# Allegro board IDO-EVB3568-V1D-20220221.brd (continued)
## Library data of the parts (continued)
D2-D9 D11-D14 D19 D20 D22-D46 D54 D55 D59 D61-D65 D94-D102 D108-D111 = DI-ESD
D15-D18 D21 D47 D48 D52 D53 D57 D58 D66-D70 = DI-ESD-MKT642U05
D71-D74 = DI-ESD-SRV05-4
D75 D104-D106 = DI-TVS-D
D78 D81 D85 D87 D89 D91 D103 = DI-TVS-BST23A122V
F1 = FUSE-SMD1812: User Part Number: HAMP; Tolerance: #TOL
F2-F15 = FUSE-SMD1206
H1-H4 = HOLE: User Part Number: pn; Tolerance: RichardLC
H5 = HOLE: Tolerance: RichardLC; User Part Number: pn
J1 = J-H-4P
J2 = J-DC-044A-2_5
J3 = J-TF-01A
J4 = J-A-3P: Tolerance: #TOL; User Part Number: HAMP
J5 = J-USB-4AFX2-DIP_1
J6 = SATA_DIP_0
J7 J16 = J-H-2P
J8 J9 = J-USB-4AFx2-DIP_2: Tolerance: #TOL; User Part Number: HAMP
J10-J12 = J-H-4P_0
J13 J21 J27 = J-H-6P
J14 = J-H-8P
J15 = J-PJ-316A-6A
J17 J32-J36 = J-A-4P: Tolerance: #TOL; User Part Number: HAMP
J18 = J-HDMI-19P
J19 = J-HDR-D-20: User Part Number: pn; Tolerance: RichardLC
J20 J25 = J-HDR-6: User Part Number: pn; Tolerance: RichardLC
J22 J23 = J-FPC05-40P: User Part Number: DENG
J24 = J-FPC05-6P: User Part Number: DENG
J26 = J-HDR-D-30: User Part Number: pn; Tolerance: RichardLC
J28 = J-FPC05-24P
J29 = RF-IPEX-20279
J30 J31 = J-RJ45-HR911130C: User Part Number: HAMP; Tolerance: #TOL
J39 = J-A-5P: Tolerance: #TOL; User Part Number: HAMP
J40 = J-A-2P
J41 = J-MINIPCIE-52P_0
L1-L3 L27 L28 L31-L33 L49 = L-IND
L5-L10 L12 L14 L15 L23-L26 L46 L47 = L-CMLS-ACM2012
L11 L13 L16-L22 L29 L30 L48 = FB-0603
L34-L45 = FB-0402
L50 = L-CMLS-ACM2012-1
LED1 = D-LED-DIP-2: User Part Number: DENG
LED2 = D-LED0603
M1-M4 = MARK
M5 = MODE-204P_2
Q1 Q2 Q7 Q10 Q13 Q16 = S-NPN
Q3-Q5 Q8 Q11 Q15 Q17 = N-MOS-Q
Q6 Q9 Q12 = P-MOS
R3-R10 R12-R37 R39-R57 R59-R62 R68-R105 R108-R116 R119-R122 R125-R166 R168 R170-R173 R175-R179 R181-R264 R266-R278 R282 R284 R286-R288 R291 R293-R295 R299-R302 R305-R309 R312 R313 R316-R367 R370-R391 = R-0402
R106 R107 R117 R118 R174 R265 R368 R369 = R-0805
R289 R292 R296 R298 R303 R304 R310 R311 = R-0603
R290 R297 = R-1206
SIM1 = J-SIM-021_0
SW1 = SW-K2-1109DE-C4SW-01
TP1-TP27 = TP-TEST: User Part Number: pn; Tolerance: RichardLC
U1 U39 = U-SY8105ADC_0
U2 U37 = U-TLV62569DBVR
U4-U7 U9-U12 U40 = U-SY6280AAC
U8 = U-FE2.1: User Part Number: HAMP; Tolerance: #TOL
U13 = U-NS4205
U14 U18 = U-74LVC1G125GW-125
U15 U16 = U-SY7201A_2
U17 = GM8775C
U19 = U-ME6211C18M5G-N
U20 = U-ME6211C15M5G-N
U21 = U-ME6211C28M5G-N
U23 = MODULE_AP6XXX
U24 U25 = Ethernet_RTL8211F
U26 U27 = U-SP3232EEN-L-TR
U28 U30 = U-MC74VHC1G04DFT2G
U29 U31 = U-SP485EEN-L-TR
U32 U33 = U-TJA1057GT-3J
U34 = U-PCF85063ATT
U35 = Sensor_MPU6500_1
U36 = PCIE_M2_NGFF-B-KEY_2
U38 = 5962-87786_1
XT1 XT3-XT5 = XTAL-4P
XT6 = XTAL-2P

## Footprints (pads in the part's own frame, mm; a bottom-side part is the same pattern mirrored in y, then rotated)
C0402L
  rect 0.49x0.54 smd: 1(-0.43,0) 2(0.43,0)
C0603L
  rect 0.75x0.9 smd: 1(-0.7,0) 2(0.7,0)
C0805L
  rect 0.95x1.35 smd: 1(-0.8,0) 2(0.8,0)
C1206L
  rect 0.95x1.7 smd: 1(-1.4,0) 2(1.4,0)
CAPAE660X770
  rect 3.15x1.6 smd: 1(-2.45,0) 2(2.45,0)
CMLP-ACM4532
  rect 1.2x1 smd: 1(-1.65,1.15) 2(-1.65,-1.15) 3(1.65,-1.15) 4(1.65,1.15)
CMLS-ACM2012
  rect 0.7x0.45 smd: 1(-0.85,0.4) 2(-0.85,-0.4) 3(0.85,-0.4) 4(0.85,0.4)
DC-044A-2_5
  round 2.3 hole 2.3 unplated: (4.1,0)
  rect 3x1.6 hole 2x0.8: 2(10.201,5.199) 3(10.201,0) 4(10.201,-3.401)
  rect 2.5x1 hole 2x0.6: 5(3,6.149) 6(3,-3.65)
DURAL_USB_AF_2X
  round 1.001 hole 0.701: 1(-3.5,0.686) 2(-1.001,0.686) 3(1.001,0.686) 4(3.5,0.686) 10(-3.5,3.327) 11(-1.001,3.327) 12(1.001,3.327) 13(3.5,3.327)
  round 2.901 hole 2.311: S1(-6.571,3.68) S2(6.571,3.68) S3(-6.571,-1.999) S4(6.571,-1.999)
ESD-DFN2510A-10
  rect 0.2x0.68 smd: 1(-1,-0.437) 2(-0.5,-0.437) 4(0.5,-0.437) 5(1,-0.437) 6(1,0.437) 7(0.5,0.437) 9(-0.5,0.437) 10(-1,0.437)
  rect 0.4x0.75 smd: 3(0,-0.395) 8(0,0.395)
FE2_1-LQFP48
  oval 1.651x0.279 smd: 1(-4.275,2.751) 2(-4.275,2.25) 3(-4.275,1.75) 4(-4.275,1.25) 5(-4.275,0.749) 6(-4.275,0.249) 7(-4.275,-0.249) 8(-4.275,-0.749) 9(-4.275,-1.25) 10(-4.275,-1.75) 11(-4.275,-2.25) 12(-4.275,-2.751) 25(4.275,-2.751) 26(4.275,-2.25) 27(4.275,-1.75) 28(4.275,-1.25) 29(4.275,-0.749) 30(4.275,-0.249) 31(4.275,0.249) 32(4.275,0.749) 33(4.275,1.25) 34(4.275,1.75) 35(4.275,2.25) 36(4.275,2.751)
  oval 0.279x1.651 smd: 13(-2.751,-4.275) 14(-2.25,-4.275) 15(-1.75,-4.275) 16(-1.25,-4.275) 17(-0.749,-4.275) 18(-0.249,-4.275) 19(0.249,-4.275) 20(0.749,-4.275) 21(1.25,-4.275) 22(1.75,-4.275) 23(2.25,-4.275) 24(2.751,-4.275) 37(2.751,4.275) 38(2.25,4.275) 39(1.75,4.275) 40(1.25,4.275) 41(0.749,4.275) 42(0.249,4.275) 43(-0.249,4.275) 44(-0.749,4.275) 45(-1.25,4.275) 46(-1.75,4.275) 47(-2.25,4.275) 48(-2.751,4.275)
FPC05-FDW-6P
  rect 0.305x1.27 smd: 1(1.25,1.575) 2(0.75,1.575) 3(0.25,1.575) 4(-0.25,1.575) 5(-0.75,1.575) 6(-1.25,1.575)
  rect 1.803x3.048 smd: 7(3.05,-1.27) 8(-3.05,-1.27)
FPC05-FDW-40P
  rect 0.305x1.27 smd: 1(9.751,1.575) 2(9.251,1.575) 3(8.75,1.575) 4(8.25,1.575) 5(7.749,1.575) 6(7.249,1.575) 7(6.749,1.575) 8(6.251,1.575) 9(5.751,1.575) 10(5.25,1.575) 11(4.75,1.575) 12(4.249,1.575) 13(3.749,1.575) 14(3.251,1.575) 15(2.751,1.575) 16(2.25,1.575) 17(1.75,1.575) 18(1.25,1.575) 19(0.749,1.575) 20(0.249,1.575) 21(-0.249,1.575) 22(-0.749,1.575) 23(-1.25,1.575) 24(-1.75,1.575) 25(-2.25,1.575) 26(-2.751,1.575) 27(-3.251,1.575) 28(-3.749,1.575) 29(-4.249,1.575) 30(-4.75,1.575) 31(-5.25,1.575) 32(-5.751,1.575) 33(-6.251,1.575) 34(-6.749,1.575) 35(-7.249,1.575) 36(-7.749,1.575) 37(-8.25,1.575) 38(-8.75,1.575) 39(-9.251,1.575) 40(-9.751,1.575)
  rect 1.803x3.048 smd: 41(11.549,-1.001) 42(-11.549,-1.001)
FPC05-ZDW-24P
  rect 1.2x0.4 smd: 1(-0.975,5.75) 2(0.975,5.25) 3(-0.975,4.75) 4(0.975,4.25) 5(-0.975,3.75) 6(0.975,3.25) 7(-0.975,2.75) 8(0.975,2.25) 9(-0.975,1.75) 10(0.975,1.25) 11(-0.975,0.75) 12(0.975,0.25) 13(-0.975,-0.25) 14(0.975,-0.75) 15(-0.975,-1.25) 16(0.975,-1.75) 17(-0.975,-2.25) 18(0.975,-2.75) 19(-0.975,-3.25) 20(0.975,-3.75) 21(-0.975,-4.25) 22(0.975,-4.75) 23(-0.975,-5.25) 24(0.975,-5.75)
  rect 2.4x2 smd: 25(0,7.55) 26(0,-7.55)
HDMIA19_HDMI_01A-NEW
  rect 0.3x2.6 smd: 1(0,0) 2(0.5,0) 3(1,0) 4(1.5,0) 5(2,0) 6(2.5,0) 7(3,0) 8(3.5,0) 9(4,0) 10(4.5,0) 11(5,0) 12(5.5,0) 13(6,0) 14(6.5,0) 15(7,0) 16(7.5,0) 17(8,0) 18(8.5,0) 19(9,0)
  oval 1.5x3.5 hole 0.9x2.7: 20(11.75,0.76) 21(-2.75,0.76)
  oval 1.5x2.5 hole 0.9x1.7: 22(-2.75,6.72) 23(11.75,6.72)
HDR200MA-1X6
  rect 1.5x1.5 hole 0.8: 1(0,0)
  round 1.5 hole 0.8: 2(2,0) 3(4,0) 4(6,0) 5(8,0) 6(10,0)
HDR200MRA-2X10
  rect 1.5x1.5 hole 0.7: 1(0,0)
  round 1.3 hole 0.7: 2(0,2) 3(2,0) 4(2,2) 5(4,0) 6(4,2) 7(6,0) 8(6,2) 9(8,0) 10(8,2) 11(10,0) 12(10,2) 13(12,0) 14(12,2) 15(14,0) 16(14,2) 17(16,0) 18(16,2) 19(18,0) 20(18,2)
HDR200MRA-2X15
  rect 1.5x1.5 hole 0.7: 1(0,0)
  round 1.3 hole 0.7: 2(0,2) 3(2,0) 4(2,2) 5(4,0) 6(4,2) 7(6,0) 8(6,2) 9(8,0) 10(8,2) 11(10,0) 12(10,2) 13(12,0) 14(12,2) 15(14,0) 16(14,2) 17(16,0) 18(16,2) 19(18,0) 20(18,2) 21(20,0) 22(20,2) 23(22,0) 24(22,2) 25(24,0) 26(24,2) 27(26,0) 28(26,2) 29(28,0) 30(28,2)
HR911130X
  round 2.997 hole 3.251 unplated: (-5.715,-3.051) (5.715,-3.051)
  round 1.524 hole 0.889: 1(5.715,-11.941) 2(4.445,-9.401) 3(3.175,-11.941) 4(1.905,-9.401) 5(0.635,-11.941) 6(-0.635,-9.401) 7(-1.905,-11.941) 8(-3.175,-9.401) 9(-4.445,-11.941) 10(-5.715,-9.401)
  round 1.651 hole 1.016: 11(6.624,1.849) 12(4.084,1.849) 13(-4.084,1.849) 14(-6.624,1.849)
  round 2.54 hole 1.651: SH1(-7.846,-6.101) SH2(7.846,-6.101)
IPEX-20279-001E
  rect 1.2x0.8 smd: 1(-1.525,0)
  rect 1.5x1.2 smd: 2(1.8,0)
  rect 2.65x1.2 smd: 3(0,-1.5) 4(0,1.5)
L0402
  rect 0.59x0.72 smd: 1(-0.48,0) 2(0.48,0)
L0603
  rect 0.8x1.02 smd: 1(-0.65,0) 2(0.65,0)
L2520
  rect 0.7x2 smd: 1(-1.05,0) 2(1.05,0)
L4040
  rect 1.65x3.35 smd: 1(-1.5,0) 2(1.5,0)
LED0603
  rect 0.9x0.95 smd: A(0.8,0) C(-0.8,0)
LED_P254_2X2DIP
  round 1.422 hole 0.914: 1(-1.27,-1.27) 2(1.27,-1.27) 3(-1.27,1.27) 4(1.27,1.27)
M_MINIPCIE_SOCKET_CK
  round 1.143 hole 1.143 unplated: (-12.499,0)
  round 1.651 hole 1.651 unplated: (12.499,0)
  rect 0.508x2.032 smd: 1(11.801,4.1) 2(11.399,-4.1) 3(11.001,4.1) 4(10.599,-4.1) 5(10.201,4.1) 6(9.799,-4.1) 7(9.4,4.1) 8(8.999,-4.1) 9(8.6,4.1) 10(8.199,-4.1) 11(7.8,4.1) 12(7.399,-4.1) 13(7,4.1) 14(6.599,-4.1) 15(6.2,4.1) 16(5.801,-4.1) 17(2.2,4.1) 18(1.801,-4.1) 19(1.399,4.1) 20(1.001,-4.1) 21(0.599,4.1) 22(0.201,-4.1) 23(-0.201,4.1) 24(-0.599,-4.1) 25(-1.001,4.1) 26(-1.399,-4.1) 27(-1.801,4.1) 28(-2.2,-4.1) 29(-2.601,4.1) 30(-3,-4.1) 31(-3.401,4.1) 32(-3.8,-4.1) 33(-4.201,4.1) 34(-4.6,-4.1) 35(-4.999,4.1) 36(-5.4,-4.1) 37(-5.801,4.1) 38(-6.2,-4.1) 39(-6.599,4.1) 40(-7,-4.1) 41(-7.399,4.1) 42(-7.8,-4.1) 43(-8.199,4.1) 44(-8.6,-4.1) 45(-8.999,4.1) 46(-9.4,-4.1) 47(-9.799,4.1) 48(-10.201,-4.1) 49(-10.599,4.1) 50(-11.001,-4.1) 51(-11.399,4.1) 52(-11.801,-4.1)
  rect 2.413x3.302 smd: 55(-14.651,3.5) 56(14.651,3.5)
MARK
  round 1 smd: 1(0,0)
MD44_AP6XXX
  rect 1.2x0.5 smd: 1(-5.7,4.5) 2(-5.7,3.6) 3(-5.7,2.7) 4(-5.7,1.8) 5(-5.7,0.9) 6(-5.7,0) 7(-5.7,-0.9) 8(-5.7,-1.8) 9(-5.7,-2.7) 10(-5.7,-3.6) 11(-5.7,-4.5) 23(5.7,-4.5) 24(5.7,-3.6) 25(5.7,-2.7) 26(5.7,-1.8) 27(5.7,-0.9) 28(5.7,0) 29(5.7,0.9) 30(5.7,1.8) 31(5.7,2.7) 32(5.7,3.6) 33(5.7,4.5)
  rect 0.5x1.2 smd: 12(-4.5,-5.7) 13(-3.6,-5.7) 14(-2.7,-5.7) 15(-1.8,-5.7) 16(-0.9,-5.7) 17(0,-5.7) 18(0.9,-5.7) 19(1.8,-5.7) 20(2.7,-5.7) 21(3.6,-5.7) 22(4.5,-5.7) 34(4.5,5.7) 35(3.6,5.7) 36(2.7,5.7) 37(1.8,5.7) 38(0.9,5.7) 39(0,5.7) 40(-0.9,5.7) 41(-1.8,5.7) 42(-2.7,5.7) 43(-3.6,5.7) 44(-4.5,5.7)
  round 0.6 smd: 45(-2.7,3.6) 46(-0.9,3.6) 47(0.9,3.6)
MPU6500-QFN-24
  custom 0.05x0.05 smd: 1(-1.55,1) 2(-1.55,0.6) 3(-1.55,0.2) 4(-1.55,-0.2) 5(-1.55,-0.6) 6(-1.55,-1) 7(-1,-1.55) 8(-0.6,-1.55) 9(-0.2,-1.55) 10(0.2,-1.55) 11(0.6,-1.55) 12(1,-1.55) 13(1.55,-1) 14(1.55,-0.6) 15(1.55,-0.2) 16(1.55,0.2) 17(1.55,0.6) 18(1.55,1) 19(1,1.55) 20(0.6,1.55) 21(0.2,1.55) 22(-0.2,1.55) 23(-0.6,1.55) 24(-1,1.55)
  custom 0.375x0.375 smd: 25(0,0)
MTG250_600
  round 6 hole 1.7: 1(0,0)
MTG300_500
  round 5 hole 3: 1(0,0)
MX125T-S-2A
  rect 0.635x1.6 smd: 1(-0.625,0) 2(0.625,0)
  rect 2.134x3.048 smd: 3(3.175,2.9) 4(-3.175,2.9)
MX125T-S-3A
  rect 0.813x1.626 smd: 1(-1.25,2.9) 2(0,2.9) 3(1.25,2.9)
  rect 2.134x3.048 smd: 4(3.8,0) 5(-3.8,0)
NS4205-SOP16
  rect 1.905x0.635 smd: 1(0,0) 2(0,-1.27) 3(0,-2.54) 4(0,-3.81) 5(0,-5.08) 6(0,-6.35) 7(0,-7.62) 8(0,-8.89) 9(6.096,-8.89) 10(6.096,-7.62) 11(6.096,-6.35) 12(6.096,-5.08) 13(6.096,-3.81) 14(6.096,-2.54) 15(6.096,-1.27) 16(6.096,0)
PB-SIDE-P-4_5X4_5
  round 1.3 hole 0.8: 1(0,0) 2(0,-3.1) 3(-1.95,-1.55)
PCA9539PW-TSSOP24
  oval 1.5x0.45 smd: 1(-3.5,3.575) 2(-3.5,2.925) 3(-3.5,2.275) 4(-3.5,1.625) 5(-3.5,0.975) 6(-3.5,0.325) 7(-3.5,-0.325) 8(-3.5,-0.975) 9(-3.5,-1.625) 10(-3.5,-2.275) 11(-3.5,-2.925) 12(-3.5,-3.575) 13(3.5,-3.575) 14(3.5,-2.925) 15(3.5,-2.275) 16(3.5,-1.625) 17(3.5,-0.975) 18(3.5,-0.325) 19(3.5,0.325) 20(3.5,0.975) 21(3.5,1.625) 22(3.5,2.275) 23(3.5,2.925) 24(3.5,3.575)
PCF85063ATT-TSSOP8
  rect 1.905x0.381 smd: 1(-2.1,0.975) 2(-2.1,0.325) 3(-2.1,-0.325) 4(-2.1,-0.975) 5(2.1,-0.975) 6(2.1,-0.325) 7(2.1,0.325) 8(2.1,0.975)
PCIE_M2_NGFF-B-KEY
  round 1.6 hole 1.6 unplated: (0,0)
  round 1.092 hole 1.092 unplated: (20.003,0)
  rect 0.305x1.549 smd: 1(19.251,-5.278) 2(18.999,2.273) 3(18.75,-5.278) 4(18.504,2.273) 5(18.247,-5.278) 6(17.996,2.273) 7(17.752,-5.278) 8(17.501,2.273) 9(17.249,-5.278) 10(17.005,2.273) 11(16.749,-5.278) 20(14.503,2.273) 21(14.249,-5.278) 22(14,2.273) 23(13.749,-5.278) 24(13.5,2.273) 25(13.249,-5.278) 26(13,2.273) 27(12.748,-5.278) 28(12.499,2.273) 29(12.248,-5.278) 30(11.999,2.273) 31(11.748,-5.278) 32(11.501,2.273) 33(11.25,-5.278) 34(11.001,2.273) 35(10.749,-5.278) 36(10.503,2.273) 37(10.251,-5.278) 38(10,2.273) 39(9.751,-5.278) 40(9.5,2.273) 41(9.251,-5.278) 42(8.999,2.273) 43(8.75,-5.278) 44(8.501,2.273) 45(8.25,-5.278) 46(8.001,2.273) 47(7.75,-5.278) 48(7.501,2.273) 49(7.252,-5.278) 50(7,2.273) 51(6.749,-5.278) 52(6.5,2.273) 53(6.253,-5.278) 54(6.002,2.273) 55(5.751,-5.278) 56(5.502,2.273) 57(5.25,-5.278) 58(5.001,2.273) 59(4.75,-5.278) 60(4.501,2.273) 61(4.249,-5.278) 62(4,2.273) 63(3.749,-5.278) 64(3.5,2.273) 65(3.249,-5.278) 66(3,2.273) 67(2.751,-5.278) 68(2.502,2.273) 69(2.243,-5.278) 70(2.002,2.273) 71(1.75,-5.278) 72(1.501,2.273) 73(1.25,-5.278) 74(1.001,2.273) 75(0.749,-5.278)
  round 6 hole 4.2: MH1(9.995,49.686)
  rect 1.194x2.743 smd: MTG76(20.358,-4.496) MTG77(-0.343,-4.496)
PH200-2A
  rect 1.524x1.524 hole 1.016: 1(4.064,0)
  round 1.524 hole 1.016: 2(2.032,0)
PH200-4A
  rect 1.27x1.27 hole 0.813: 1(6.096,0)
  round 1.27 hole 0.813: 2(4.064,0) 3(2.032,0) 4(0,0)
PH200-6A
  rect 1.27x1.27 hole 0.813: 1(6.096,0)
  round 1.27 hole 0.813: 2(4.064,0) 3(2.032,0) 4(0,0) 5(-2.032,0) 6(-4.064,0)
PH200-6AW
  rect 1.524x1.524 hole 1.016: 1(4.064,0)
  round 1.524 hole 1.016: 2(2.032,0) 3(0,0) 4(-2.032,0) 5(-4.039,0) 6(-6.045,0)
PH200-8A
  rect 1.27x1.27 hole 0.813: 1(6.096,0)
  round 1.27 hole 0.813: 2(4.064,0) 3(2.032,0) 4(0,0) 5(-2.032,0) 6(-4.064,0) 7(-6.096,0) 8(-8.128,0)
PH200-S-4AWZ
  rect 1.016x7.5 smd: 1(-3,2) 2(-1,2) 3(1,2) 4(3,2)
  rect 1.524x3.404 smd: 5(-5.35,5.75) 6(5.35,5.75)
PH200-S-5AWZ
  rect 1.016x7.5 smd: 1(-3,2) 2(-1,2) 3(1,2) 4(3,2) 5(5,2)
  rect 1.524x3.404 smd: 6(-5.35,5.75) 7(7.35,5.75)
PJ-316A-6A
  round 1.397 hole 1.397 unplated: (-10.55,0)
  rect 1.778x2.159 smd: 1(-2.75,3.75) 2(-9.3,-4.15) 3(-5.5,3.75) 4(-2.75,-4.15) 5(-11.5,-4.15) 6(-10.55,3.75)
QFN50P700X700X100-49AN
  custom 0.075x0.075 smd: 1(-3.45,2.75) 2(-3.45,2.25) 3(-3.45,1.75) 4(-3.45,1.25) 5(-3.45,0.75) 6(-3.45,0.25) 7(-3.45,-0.25) 8(-3.45,-0.75) 9(-3.45,-1.25) 10(-3.45,-1.75) 11(-3.45,-2.25) 12(-3.45,-2.75) 13(-2.75,-3.45) 14(-2.25,-3.45) 15(-1.75,-3.45) 16(-1.25,-3.45) 17(-0.75,-3.45) 18(-0.25,-3.45) 19(0.25,-3.45) 20(0.75,-3.45) 21(1.25,-3.45) 22(1.75,-3.45) 23(2.25,-3.45) 24(2.75,-3.45) 25(3.45,-2.75) 26(3.45,-2.25) 27(3.45,-1.75) 28(3.45,-1.25) 29(3.45,-0.75) 30(3.45,-0.25) 31(3.45,0.25) 32(3.45,0.75) 33(3.45,1.25) 34(3.45,1.75) 35(3.45,2.25) 36(3.45,2.75) 37(2.75,3.45) 38(2.25,3.45) 39(1.75,3.45) 40(1.25,3.45) 41(0.75,3.45) 42(0.25,3.45) 43(-0.25,3.45) 44(-0.75,3.45) 45(-1.25,3.45) 46(-1.75,3.45) 47(-2.25,3.45) 48(-2.75,3.45)
  rect 5.25x5.25 smd: 49(0,0)
R0402L
  rect 0.47x0.52 smd: 1(-0.43,0) 2(0.43,0)
R0603L
  rect 0.7x0.92 smd: 1(-0.6,0) 2(0.6,0)
R0805L
  rect 0.85x1.3 smd: 1(-0.85,0) 2(0.85,0)
R1206L
  rect 0.85x1.7 smd: 1(-1.4,0) 2(1.4,0)
RTL8211F-CG-QFN40
  rect 0.7x0.2 smd: 1(-2.35,1.8) 2(-2.35,1.4) 3(-2.35,1) 4(-2.35,0.6) 5(-2.35,0.2) 6(-2.35,-0.2) 7(-2.35,-0.6) 8(-2.35,-1) 9(-2.35,-1.4) 10(-2.35,-1.8) 21(2.35,-1.8) 22(2.35,-1.4) 23(2.35,-1) 24(2.35,-0.6) 25(2.35,-0.2) 26(2.35,0.2) 27(2.35,0.6) 28(2.35,1) 29(2.35,1.4) 30(2.35,1.8)
  rect 0.2x0.7 smd: 11(-1.8,-2.35) 12(-1.4,-2.35) 13(-1,-2.35) 14(-0.6,-2.35) 15(-0.2,-2.35) 16(0.2,-2.35) 17(0.6,-2.35) 18(1,-2.35) 19(1.4,-2.35) 20(1.8,-2.35) 31(1.8,2.35) 32(1.4,2.35) 33(1,2.35) 34(0.6,2.35) 35(0.2,2.35) 36(-0.2,2.35) 37(-0.6,2.35) 38(-1,2.35) 39(-1.4,2.35) 40(-1.8,2.35)
  rect 3.2x3.2 smd: 41(0,0)
SATA30_7P_V_DIP
  oval 0.92x1.27 hole 0.74: 1(0,0) 2(-1.27,1) 3(-2.54,1) 4(-3.81,0) 5(-5.08,1) 6(-6.35,1) 7(-7.62,0)
  round 2.35 hole 1.35: 8(2.67,0.5) 9(-10.29,0.5)
SIM-91288-021
  rect 2.54x1.397 smd: C1(-0.051,12.319) C2(-0.051,9.779) C3(-0.051,7.239) C5(-23.622,12.319) C6(-23.622,9.779) C7(-23.622,7.239) CD1(-0.051,-0.051) CD2(-23.622,-0.051)
SMA_DO-214AC
  rect 1.85x1.45 smd: A(1.95,0) C(-1.95,0)
SMAF
  rect 1.43x1.53 smd: A(-1.84,0) C(1.84,0)
SMD1206
  rect 1.25x1.65 smd: 1(-1.5,0) 2(1.5,0)
SMD1812
  rect 2.032x3.302 smd: 1(-2.159,0) 2(2.159,0)
SOD123
  rect 0.8x0.75 smd: A(1.7,0) C(-1.7,0)
SOD523
  rect 0.65x0.5 smd: A(0.9,0) C(-0.9,0)
SOM3568-204P
  oval 0.55x1.4 smd: 1(2.489,0.708) 2(3.489,0.708) 3(4.489,0.708) 4(5.489,0.708) 5(6.489,0.708) 6(7.489,0.708) 7(8.489,0.708) 8(9.489,0.708) 9(10.489,0.708) 10(11.489,0.708) 11(12.489,0.708) 12(13.489,0.708) 13(14.489,0.708) 14(15.489,0.708) 15(16.489,0.708) 16(17.489,0.708) 17(18.489,0.708) 18(19.489,0.708) 19(20.489,0.708) 20(21.489,0.708) 21(22.489,0.708) 22(23.489,0.708) 23(24.489,0.708) 24(25.489,0.708) 25(26.489,0.708) 26(27.489,0.708) 27(28.489,0.708) 28(29.489,0.708) 29(30.489,0.708) 30(31.489,0.708) 31(32.489,0.708) 32(33.489,0.708) 33(34.489,0.708) 34(35.489,0.708) 35(36.489,0.708) 36(37.489,0.708) 37(38.489,0.708) 38(39.489,0.708) 39(40.489,0.708) 40(41.489,0.708) 41(42.489,0.708) 42(43.489,0.708) 43(44.489,0.708) 44(45.489,0.708) 45(46.489,0.708) 46(47.489,0.708) 47(48.489,0.708) 48(49.489,0.708) 49(50.489,0.708) 50(51.489,0.708) 51(52.489,0.708) 52(53.489,0.708) 53(54.489,0.708) 54(55.489,0.708) 55(56.489,0.708) 56(57.489,0.708) 57(58.489,0.708) 58(59.489,0.708) 103(59.489,47.044) 104(58.489,47.044) 105(57.489,47.044) 106(56.489,47.044) 107(55.489,47.044) 108(54.489,47.044) 109(53.489,47.044) 110(52.489,47.044) 111(51.489,47.044) 112(50.489,47.044) 113(49.489,47.044) 114(48.489,47.044) 115(47.489,47.044) 116(46.489,47.044) 117(45.489,47.044) 118(44.489,47.044) 119(43.489,47.044) 120(42.489,47.044) 121(41.489,47.044) 122(40.489,47.044) 123(39.489,47.044) 124(38.489,47.044) 125(37.489,47.044) 126(36.489,47.044) 127(35.489,47.044) 128(34.489,47.044) 129(33.489,47.044) 130(32.489,47.044) 131(31.489,47.044) 132(30.489,47.044) 133(29.489,47.044) 134(28.489,47.044) 135(27.489,47.044) 136(26.489,47.044) 137(25.489,47.044) 138(24.489,47.044) 139(23.489,47.044) 140(22.489,47.044) 141(21.489,47.044) 142(20.489,47.044) 143(19.489,47.044) 144(18.489,47.044) 145(17.489,47.044) 146(16.489,47.044) 147(15.489,47.044) 148(14.489,47.044) 149(13.489,47.044) 150(12.489,47.044) 151(11.489,47.044) 152(10.489,47.044) 153(9.489,47.044) 154(8.489,47.044) 155(7.489,47.044) 156(6.489,47.044) 157(5.489,47.044) 158(4.489,47.044) 159(3.489,47.044) 160(2.489,47.044)
  oval 1.4x0.55 smd: 59(61.268,2.377) 60(61.268,3.377) 61(61.268,4.377) 62(61.268,5.377) 63(61.268,6.377) 64(61.268,7.377) 65(61.268,8.377) 66(61.268,9.377) 67(61.268,10.377) 68(61.268,11.377) 69(61.268,12.377) 70(61.268,13.377) 71(61.268,14.377) 72(61.268,15.377) 73(61.268,16.377) 74(61.268,17.377) 75(61.268,18.377) 76(61.268,19.377) 77(61.268,20.377) 78(61.268,21.377) 79(61.268,22.377) 80(61.268,23.377) 81(61.268,24.377) 82(61.268,25.377) 83(61.268,26.377) 84(61.268,27.377) 85(61.268,28.377) 86(61.268,29.377) 87(61.268,30.377) 88(61.268,31.377) 89(61.268,32.377) 90(61.268,33.377) 91(61.268,34.377) 92(61.268,35.377) 93(61.268,36.377) 94(61.268,37.377) 95(61.268,38.377) 96(61.268,39.377) 97(61.268,40.377) 98(61.268,41.377) 99(61.268,42.377) 100(61.268,43.377) 101(61.268,44.377) 102(61.268,45.377) 161(0.708,45.377) 162(0.708,44.377) 163(0.708,43.377) 164(0.708,42.377) 165(0.708,41.377) 166(0.708,40.377) 167(0.708,39.377) 168(0.708,38.377) 169(0.708,37.377) 170(0.708,36.377) 171(0.708,35.377) 172(0.708,34.377) 173(0.708,33.377) 174(0.708,32.377) 175(0.708,31.377) 176(0.708,30.377) 177(0.708,29.377) 178(0.708,28.377) 179(0.708,27.377) 180(0.708,26.377) 181(0.708,25.377) 182(0.708,24.377) 183(0.708,23.377) 184(0.708,22.377) 185(0.708,21.377) 186(0.708,20.377) 187(0.708,19.377) 188(0.708,18.377) 189(0.708,17.377) 190(0.708,16.377) 191(0.708,15.377) 192(0.708,14.377) 193(0.708,13.377) 194(0.708,12.377) 195(0.708,11.377) 196(0.708,10.377) 197(0.708,9.377) 198(0.708,8.377) 199(0.708,7.377) 200(0.708,6.377) 201(0.708,5.377) 202(0.708,4.377) 203(0.708,3.377) 204(0.708,2.377)
  rect 1.524x1.524 smd: 205(3.81,8.895) 206(3.81,11.405) 207(3.81,13.914)
SOP8-P127-390X490
  rect 1.35x0.55 smd: 1(-2.6,1.905) 2(-2.6,0.635) 3(-2.6,-0.635) 4(-2.6,-1.905) 5(2.6,-1.905) 6(2.6,-0.635) 7(2.6,0.635) 8(2.6,1.905)
SOT23
  rect 1.05x0.65 smd: 1(-1.15,0.95) 2(-1.15,-0.95) 3(1.15,0)
SOT23-5
  rect 1.1x0.6 smd: 1(-1.35,0.95) 2(-1.35,0) 3(-1.35,-0.95) 4(1.35,-0.95) 5(1.35,0.95)
SOT23-6
  rect 1.05x0.6 smd: 1(-1.35,0.95) 2(-1.35,0) 3(-1.35,-0.95) 4(1.35,-0.95) 5(1.35,0) 6(1.35,0.95)
SOT353
  rect 0.95x0.4 smd: 1(-1.1,0.65) 2(-1.1,0) 3(-1.1,-0.65) 4(1.1,-0.65) 5(1.1,0.65)
SOT523
  rect 0.85x0.3 smd: 1(-0.8,0.5) 2(-0.8,-0.5) 3(0.8,0)
SOT563
  rect 0.47x0.26 smd: 1(-0.74,0.5) 2(-0.74,0) 3(-0.74,-0.5) 4(0.74,-0.5) 5(0.74,0) 6(0.74,0.5)
SP3232EEY-TSSOP-16
  rect 1.45x0.45 smd: 1(-2.901,2.276) 2(-2.901,1.626) 3(-2.901,0.975) 4(-2.901,0.325) 5(-2.901,-0.325) 6(-2.901,-0.975) 7(-2.901,-1.626) 8(-2.901,-2.276) 9(2.901,-2.276) 10(2.901,-1.626) 11(2.901,-0.975) 12(2.901,-0.325) 13(2.901,0.325) 14(2.901,0.975) 15(2.901,1.626) 16(2.901,2.276)
TF-01A
  round 0.1 hole 1: (-7.2,-10.5) (0.8,-10.5)
  oval 0.7x2.3 smd: 1(0,0.2) 2(-1.1,0.2) 3(-2.2,0.2) 4(-3.3,0.2) 5(-4.4,0.2) 6(-5.5,0.2) 7(-6.6,0.2) 8(-7.7,0.2) 9(-8.8,0.2)
  rect 1.2x1.4 smd: 10(-10,-0.5)
  rect 1.6x1.4 smd: 11(4.6,-0.5)
  rect 1.2x2.2 smd: 12(-10,-10.2) 13(5.5,-10.2)
TP100
  round 1 smd: 1(0,0)
USB3D0_AF_18P
  round 1.118 hole 0.711: 1(-3.5,0) 2(-1,0) 3(1,0) 4(3.5,0) 5(4,1.5) 6(2,1.5) 7(0,1.5) 8(-2,1.5) 9(-4,1.5) 10(-3.5,3.2) 11(-1,3.2) 12(1,3.2) 13(3.5,3.2) 14(4,4.7) 15(2,4.7) 16(0,4.7) 17(-2,4.7) 18(-4,4.7)
  round 2.794 hole 2.362: 19(-6.57,3.68) 20(6.57,3.68) 21(6.57,-2) 22(-6.57,-2)
V0402
  rect 0.57x0.62 smd: 1(-0.48,0) 2(0.48,0)
XH250-2A
  rect 1.524x1.524 hole 0.889: 1(2.54,-1.016)
  round 1.524 hole 0.889: 2(0,-1.016)
XTAL_32X15_2P
  rect 1.09x1.9 smd: 1(-1.25,0) 2(1.25,0)
XTAL_32X25_4P
  rect 1.3x0.9 smd: 1(-0.85,1.4) 2(-0.85,-1.4) 3(0.85,-1.4) 4(0.85,1.4)

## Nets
GND: C3.1 C4.2 C6.1 C7.1 C9.1 C10.1 C11.1 C12.1 C14.1 C17.1 C18.1 C20.1 C21.1 C22.1 C23.1 C25.1 C26.1 C27.1 C30.1 C31.1 C32.1 C33.1 C34.1 C35.1 C38.1 C41.1 C43.1 C45.1 C48.1 C52.1 C53.1 C54.1 C55.1 C56.1 C57.1 C58.1 C59.1 C60.1 C61.1 C62.1 C63.1 C64.1 C65.1 C66.1 C67.1 C68.1 C69.1 C70.1 C71.1 C72.1 C73.1 C74.1 C75.1 C76.1 C77.1 C78.1 C79.1 C80.1 C81.1 C82.1 C83.1 C84.1 C85.1 C87.2 C88.2 C90.2 C91.2 C92.1 C93.1 C94.1 C95.1 C96.1 C107.1 C108.1 C110.1 C112.1 C113.1 C114.1 C115.1 C116.1 C117.1 C118.1 C119.1 C120.1 C121.1 C122.1 C123.1 C124.1 C125.1 C126.1 C127.1 C128.1 C129.1 C130.1 C131.1 C132.1 C133.1 C134.1 C135.1 C138.1 C139.1 C140.1 C142.1 C143.1 C144.1 C145.1 C146.1 C147.1 C148.1 C149.1 C150.1 C151.1 C152.1 C153.1 C155.2 C156.1 C157.1 C158.1 C161.1 C162.1 C163.1 C164.1 C166.1 C167.1 C168.1 C169.1 C170.1 C171.1 C172.1 C173.1 C174.1 C175.1 C176.1 C177.1 C178.1 C179.1 C180.1 C181.1 C182.1 C183.1 C184.1 C185.1 C186.1 C187.1 C188.1 C189.1 C190.1 C191.1 C192.1 C193.1 C194.1 C195.1 C196.1 C197.1 C199.1 C200.1 C201.1 C202.1 C203.1 C204.1 C205.1 C206.1 C207.1 C208.1 C209.1 C210.1 C211.1 C212.1 C213.1 C214.1 C215.1 C216.1 C217.1 C220.1 C221.1 C222.1 C225.1 C226.1 C227.1 C228.1 C229.1 C230.1 C231.1 C232.1 C233.1 C234.1 C235.1 C236.1 C237.1 C238.1 C239.2 C240.2 C241.1 C242.1 C243.1 C244.1 C245.1 C246.1 C247.1 C248.1 C252.1 C253.1 C254.1 C255.1 C256.1 C257.1 C258.1 C259.1 C260.1 C261.1 C262.1 C263.1 C264.1 C266.1 C267.1 C268.1 C269.1 C270.1 C271.1 C272.1 C273.1 C274.1 C275.1 C276.1 C277.1 C278.1 C482.1 C483.1 C484.1 C485.1 C486.1 C489.1 C490.1 C491.1 C493.1 C494.1 C496.1 C497.1 D2.2(I/O1) D3.2(I/O1) D4.2(I/O1) D5.2(I/O1) D6.2(I/O1) D7.2(I/O1) D8.2(I/O1) D9.2(I/O1) D11.2(I/O1) D12.2(I/O1) D13.2(I/O1) D14.2(I/O1) D15.3 D15.8 D16.3 D16.8 D17.3 D17.8 D18.3 D18.8 D19.2(I/O1) D20.2(I/O1) D21.3 D21.8 D22.2(I/O1) D23.2(I/O1) D24.2(I/O1) D25.2(I/O1) D26.2(I/O1) D27.2(I/O1) D28.2(I/O1) D29.2(I/O1) D30.2(I/O1) D31.2(I/O1) D32.2(I/O1) D33.2(I/O1) D34.2(I/O1) D35.2(I/O1) D36.2(I/O1) D37.2(I/O1) D38.2(I/O1) D39.2(I/O1) D40.2(I/O1) D41.2(I/O1) D42.2(I/O1) D43.2(I/O1) D44.2(I/O1) D45.2(I/O1) D46.2(I/O1) D47.3 D47.8 D48.3 D48.8 D52.3 D52.8 D53.3 D53.8 D54.1(I/O2) D55.1(I/O2) D57.3 D57.8 D58.3 D58.8 D59.1(I/O2) D61.1(I/O2) D62.2(I/O1) D63.2(I/O1) D64.2(I/O1) D65.2(I/O1) D66.3 D66.8 D67.3 D67.8 D68.3 D68.8 D69.3 D69.8 D70.3 D70.8 D71.2 D72.2 D73.2 D74.2 D78.3 D81.3 D85.3 D87.3 D89.3 D91.3 D94.2(I/O1) D95.2(I/O1) D96.2(I/O1) D97.2(I/O1) D98.2(I/O1) D99.2(I/O1) D100.2(I/O1) D101.2(I/O1) D102.2(I/O1) D103.3 D108.1(I/O2) D109.1(I/O2) D110.1(I/O2) D111.1(I/O2) H5.1 J3.6(VSS) J3.10(G1) J3.11(G2) J3.12(G3) J3.13(G4) J4.3 J4.4 J4.5 J5.4(GND1) J5.7(GND2) J5.13(GND3) J5.16(GND4) J5.19(SHELL1) J5.20(SHELL2) J5.21(SHELL3) J5.22(SHELL4) J6.1(GND1) J6.4(GND2) J6.7(GND3) J6.8(GND4) J6.9(GND5) J7.2 J8.4(1GND) J8.13(2GND) J8.S1(MH1) J8.S2(MH2) J8.S3(MH3) J8.S4(MH4) J9.4(1GND) J9.13(2GND) J9.S1(MH1) J9.S2(MH2) J9.S3(MH3) J9.S4(MH4) J10.4 J11.4 J12.4 J13.1 J13.6 J14.2 J14.8 J15.1(GND) J16.1 J17.5 J17.6 J18.2 J18.5 J18.8 J18.11 J18.17 J18.20 J18.21 J18.22 J18.23 J19.4 J19.13 J19.14 J21.1 J21.2 J22.11 J22.16 J22.19 J22.22 J22.25 J22.28 J22.31 J22.34 J22.37 J22.41 J22.42 J23.11 J23.16 J23.19 J23.22 J23.25 J23.28 J23.31 J23.34 J23.37 J23.41 J23.42 J24.1 J24.7 J24.8 J26.5(3) J26.6(18) J26.13(7) J26.14(22) J26.25(13) J26.26(28) J27.1 J27.2 J28.10 J28.13 J28.16 J28.19 J28.22 J28.25 J28.26 J29.1(GND1) J29.3(GND2) J29.4(GND3) J30.10(GND) J31.10(GND) J32.1 J32.5 J32.6 J33.1 J33.5 J33.6 J34.1 J34.5 J34.6 J35.1 J35.5 J35.6 J36.1 J36.5 J36.6 J39.3(6) J39.6(9) J39.7 J40.1 J40.3 J40.4 J41.4(GND#4) J41.9(GND#9) J41.15(GND#15) J41.18(GND#18) J41.21(GND#21) J41.26(GND#26) J41.27(GND#27) J41.29(GND#29) J41.34(GND#34) J41.35(GND#35) J41.37(GND#37) J41.40(GND#40) J41.43(GND#43) J41.50(GND#50) J41.55(MT3) J41.56(MT4) L50.4 LED1.2 LED1.4 M5.4(GND1) M5.5(GND2) M5.14(GND3) M5.38(GND4) M5.98(GND5) M5.105(GND6) M5.127(GND7) M5.152(GND8) M5.179(GND9) M5.194(GND10) Q1.2 Q2.2 Q7.2 Q10.2 Q13.2 Q16.2 R5.2 R6.2 R10.2 R15.2 R17.2 R29.2 R34.2 R35.2 R36.2 R37.2 R40.2 R41.2 R42.2 R43.2 R45.2 R47.2 R49.2 R52.2 R53.2 R54.2 R56.2 R57.2 R59.2 R71.2 R77.2 R86.2 R105.2 R106.2 R107.2 R116.2 R117.2 R118.2 R121.1 R125.2 R161.2 R164.2 R173.2 R179.2 R192.2 R194.2 R195.1 R199.1 R203.1 R206.1 R208.1 R210.1 R212.1 R213.1 R216.1 R239.2 R241.2 R242.1 R246.1 R250.1 R254.1 R256.1 R257.1 R259.1 R260.1 R263.1 R265.1 R289.1 R293.2 R296.1 R299.2 R301.1 R307.1 R324.2 R338.2 R341.2 R365.2 R366.2 R369.2 R375.2 R381.2 R382.2 R387.1 R389.1 R391.1 SIM1.C5(GND) SW1.2 SW1.3 TP16.1 TP17.1 TP18.1 TP19.1 TP20.1 TP21.1 TP22.1 TP23.1 U1.3(GND) U2.2(GND) U4.2(GND) U5.2(GND) U6.2(GND) U7.2(GND) U8.10(VSS1) U8.24(VS_PLL) U8.39(VSS) U9.2(GND) U10.2(GND) U11.2(GND) U12.2(GND) U13.2(PGND1) U13.11(GND1) U13.15(PGND2) U14.1(O\E\) U14.3(GND) U15.2(GND) U16.2(GND) U17.5(GND) U17.9(TEST) U17.37(VSS_PLL) U17.49(EPAD) U18.1(O\E\) U18.3(GND) U19.2(GND) U20.2(GND) U21.2(GND) U23.1(GND1) U23.3(GND2) U23.20(GND3) U23.31(GND4) U23.33(GND5) U23.36(GND6) U24.41(E_PAD) U25.41(E_PAD) U26.15(GND) U27.15(GND) U28.3(G) U29.5(GND) U30.3(G) U31.5(GND) U32.2(GND) U33.2(GND) U34.4(VSS) U35.11(FSYNC) U35.18(GND) U35.20(RESV2) U35.25(E-PAD) U36.3(GND1) U36.5(GND2) U36.11(GND3) U36.27(GND4) U36.33(GND5) U36.39(GND6) U36.45(GND7) U36.51(GND8) U36.57(GND9) U36.71(GND10) U36.73(GND11/NC) U36.MH1 U36.MTG76(NC3) U36.MTG77(NC4) U37.2(GND) U38.12(GND) U39.3(GND) U40.2(GND) XT1.2 XT1.4 XT3.2 XT3.4 XT4.2 XT4.4 XT5.2 XT5.4
GND_EARTH: C206.2 H1.1 H2.1 H3.1 H4.1 J30.SH1 J30.SH2 J31.SH1 J31.SH2 R265.2
GND_IN: C488.1 D1.A J1.1 J1.2 J2.2 J2.3 L50.1 R369.1
VBAT_RTC: D93.A J40.2
VBAT_WL_1T1R: C166.2 Q12.3(DRAIN) R174.2 U23.9(VBAT)
VBUSM: R44.1 R45.1 U8.41(VBUSM)
VCC1V5_DVP: C148.2 C149.2 C492.1 J28.3 R388.2 U20.5(OUT)
VCC1V8_DVP: C144.2 C145.2 J28.4 R148.1 R386.2 U19.5(OUT)
VCC2V8_DVP: C151.2 C152.2 J28.1 J28.2 R390.2 U21.5(OUT)
VCC3V3_PHY0: C187.2 C188.2 C189.2 C190.2 C191.2 R191.2 R196.2 R200.2 R218.1 R229.2 U24.11(AVDD33#11) U24.29(DVDD33) U24.40(AVDD33#40)
VCC3V3_PHY1: C212.2 C213.2 C214.2 C215.2 C216.2 R238.2 R243.2 R247.2 R266.1 R277.2 U25.11(AVDD33#11) U25.29(DVDD33) U25.40(AVDD33#40)
VCC3V3_SD: C35.2 D2.1(I/O2) J3.4(VDD) M5.69(VCC3V3_SD)
VCC5V0_SYS: C17.2 C18.2 C24.2 C25.2 C26.2 C27.2 C30.2 C31.2 C32.2 C33.2 C108.2 C113.2 C114.2 C121.2 C122.2 C139.2 C233.2 C236.2 C263.2 C264.2 C486.2 D83.A J20.3 J25.3 J32.4 J33.4 J34.4 J35.4 J36.4 L3.2 L13.1 L21.1 L27.1 L28.1 M5.1(VCC5V0_RTC) M5.2(VCC5V0_SYS1) M5.3(VCC5V0_SYS2) Q8.1(GATE) Q17.1(GATE) R7.1 R13.1 R44.2 R127.1 R306.1 R309.1 R367.1 R380.1 U2.4(VIN) U14.5(VCC) U15.6(VIN) U16.6(VIN) U18.5(VCC) U32.3(VCC) U33.3(VCC) U37.4(VIN)
VCC5V0_USB_FE_D1: C54.2 D20.1(I/O2) J8.10(2VBUS) U7.1(VOUT)
VCC5V0_USB_FE_D2: C57.2 D22.1(I/O2) J9.1(1VBUS) U9.1(VOUT)
VCC5V0_USB_FE_D3: C61.2 D23.1(I/O2) J9.10(2VBUS) U10.1(VOUT)
VCC5V0_USB_FE_D4: C67.2 D24.1(I/O2) J10.1 U11.1(VOUT)
VCC5V0_USB_FE_D5: C489.2 D27.1(I/O2) J11.1 U40.1(VOUT)
VCC5V0_USB_FE_D6: C78.2 D30.1(I/O2) J12.1 U12.1(VOUT)
VCC5V0_USB_HOST1: C43.2 D14.1(I/O2) J5.10(VBUS2) U5.1(VOUT)
VCC5V0_USB_HOST3: C52.2 D19.1(I/O2) J8.1(1VBUS) U6.1(VOUT)
VCC5V0_USB_OTG0: C38.2 D13.1(I/O2) J5.1(VBUS1) R28.2 U4.1(VOUT)
VCC5V_HDMI_TX: C96.2 D51.C J18.18
VCC12V_DC_IN: F1.1 J1.3 J1.4 J2.4
VCC12V_DCIN: C3.2 C4.1 C6.2 C7.2 C22.2 C23.2 J20.1 J21.5 J21.6 J25.1 J27.5 J27.6 L50.3 R3.1 R368.2 U1.1(IN) U39.1(IN)
VCC_1V8: C132.2 L30.2 M5.103(VCC_1V8) R60.1 R61.1 R146.2 R147.2 R172.1 R221.1 R269.1
VCC_1V8_HUB: C63.2 C74.2 C75.2 C76.2 U8.6(VD18_1#6) U8.21(VD_PLL) U8.25(VD18_O) U8.28(VD18_1#28)
VCC_3V3: M5.104(VCC_3V3) R14.1
VCC_3V3_HUB: C59.2 C66.2 C68.2 C69.2 C70.2 C71.2 C72.2 C73.2 L11.2 R46.2 R48.1 U8.9(VDD33_O) U8.15(VD33_1#15) U8.20(VD33_1#20) U8.26(VD33_1#26) U8.31(VD33_1#31) U8.36(VD33_1#36) U8.42(VD33_1#42)
VCC_3V8: C246.2 C247.2 C248.2 C253.2 C254.2 C255.2 C256.2 C257.2 C258.2 C259.2 C265.2 C266.2 C267.2 C273.2 C274.2 C275.2 C276.2 C277.2 C278.2 C482.2 C483.2 C484.2 C485.2 J41.2(VCC3V3#2) J41.24(NC3) J41.39(VCC3V3#39) J41.41(VCC3V3#41) J41.52(VCC3V3#52) L49.2 R334.1 R337.1 R340.1 U36.2(VBAT1) U36.4(VBAT2) U36.70(VBAT3) U36.72(VBAT4) U36.74(VBAT5)
VCC_5V_HUB: C58.2 L13.2 U8.8(VD5_1)
VCC_485: C228.2 C232.2 D83.C R292.2 R298.2 U29.8(VCC) U31.8(VCC)
VCC_EDP_OUT: C110.2 C111.2 J20.2 J20.4 J20.6 Q6.2(SOURCE) R90.1
VCC_EDP_OUT_: C112.2 J19.1 J19.2 Q6.3(DRAIN)
VCC_LEDA_TX0: C115.2 C116.2 D56.C J22.1 J22.2 U15.5(OVP)
VCC_LEDA_TX1: C119.2 C120.2 D60.C J23.1 J23.2 U16.5(OVP)
VCC_LEDK_TX0: J22.9 J22.10 R104.2 R106.1 R107.1
VCC_LEDK_TX1: J23.9 J23.10 R115.2 R117.1 R118.1
VCC_SIM: C260.2 C261.2 D97.1(I/O2) L48.2 R330.2 R339.2 SIM1.C1(VDD) U36.36(UIM_PWR)
VCCA_CODEC: C94.2 C95.2 L22.2 U13.6(VDD1) U13.9(VDD2)
VCCIO_ACODEC: L16.2 R69.2 R75.1
VCCIO_PHY0: C183.2 C184.2 C185.2 R220.2 R221.2 R222.2 U24.28(DVDD_RG)
VCCIO_PHY1: C208.2 C209.2 C210.2 R207.2 R209.2 R211.2 R214.2 R217.2 R251.2 R255.2 R258.2 R261.2 R264.2 R268.2 R269.2 R270.2 U25.28(DVDD_RG)
VCCIO_WL: C161.2 C162.2 C163.2 Q11.1(GATE) Q15.1(GATE) R152.1 R157.1 R166.1 R171.2 R172.2 R176.1 R305.1 R308.1 U23.22(VDDIO)
VDD10_PHY0: C175.2 C176.2 C177.2 C178.2 C180.2 C181.2 L32.2 U24.3(AVDD10#3) U24.8(AVDD10#8) U24.21(DVDD10) U24.38(AVDD10#38)
VDD10_PHY1: C199.2 C200.2 C201.2 C203.2 C204.2 C205.2 L33.2 U25.3(AVDD10#3) U25.8(AVDD10#8) U25.21(DVDD10) U25.38(AVDD10#38)
VDD_3V3: C19.2 C20.2 C21.2 C107.2 C117.2 C123.2 C124.2 C128.2 C143.2 C147.2 C150.2 C164.2 C165.2 C217.2 C222.2 C229.2 C231.2 C242.2 C243.2 C244.2 C268.2 D92.A J19.19 J20.5 J22.38 J22.39 J23.38 J23.39 J24.6 J25.5 L2.2 L11.1 L16.1 L22.1 L29.2 Q3.1(GATE) Q4.1(GATE) Q12.2(SOURCE) R9.1 R12.1 R25.1 R72.1 R81.1 R83.1 R87.1 R103.1 R109.2 R110.2 R119.1 R126.1 R149.1 R150.1 R151.1 R165.1 R171.1 R174.1 R175.1 R222.1 R229.1 R270.1 R277.1 R287.1 R294.1 R300.1 R302.2 R312.2 R313.2 R318.2 R319.2 R322.2 R323.1 R346.2 R347.2 R348.2 R349.2 R350.2 R351.2 R352.2 R353.2 R354.2 R355.2 R356.2 R357.2 R358.2 R359.2 R360.2 R361.2 R362.1 R363.1 R364.1 R374.1 R378.1 U19.1(VIN) U20.1(VIN) U21.1(VIN) U26.16(VCC) U27.16(VCC) U28.5(V) U30.5(V) U35.8(VDDIO) U35.13(VDD) U38.24(VDD)
VDD_LVDS: C133.2 C134.2 C135.2 L30.1 U17.35(VDD_LVDS1) U17.36(VDD_PLL) U17.38(VDD_LVDS2)
VDD_RTC: C241.2 D92.C D93.C U34.8(VDD)
VDD_USB_5V: C8.2 C9.2 C10.2 C11.2 C41.2 C45.2 C48.2 C53.2 C55.2 C56.2 C62.2 C77.2 C79.2 C490.2 D49.A D51.A J7.1 J14.1 L1.2 Q5.1(GATE) R4.1 U4.5(IN) U5.5(IN) U6.5(IN) U7.5(IN) U9.5(IN) U10.5(IN) U11.5(IN) U12.4(EN) U12.5(IN) U40.5(IN)
4G_5G_RESET_: Q16.3 R376.2 U36.67(RESET#_(1V8))
4G_5G_RESET_GPIO3_A4: M5.123(LCDC_D11/VOP_BT1120_D3/GMAC1_RX) Q16.1
4G_LED_WANN#: J41.42(LED_WWAN) LED2.C(CATHODE)
BT_REG_ON: R160.2 R161.1 R181.1
BT_REG_ON_H_GPIO3_A7: M5.120(LCDC_D14/VOP_BT1120_D5/GMAC1_RX) R160.1
BT_WAKE_HOST: Q11.2(SOURCE) R166.2 R170.2 U23.7(BT_HOST_WAKE)
BT_WAKE_HOST_H_GPIO3_A1: M5.126(LCDC_D8/VOP_BT1120_D0/SPI1_CS0_) Q11.3(DRAIN) R165.2 R170.1
CAN1_H: L46.1 U32.7(CANH)
CAN1_L: L46.2 U32.6(CANL)
CAN1_RX_M0: D90.A M5.36(I2C3_SDA_M0/UART3_RX_M0/CAN1_RX) R302.1
CAN1_RX_M0_: D90.C U32.4(RXD)
CAN1_STB_IO: R301.2 U32.8(S)
CAN1_TX_M0: M5.37(I2C3_SCL_M0/UART3_TX_M0/CAN1_TX) U32.1(TXD)
CAN1H: D89.1 D105.A(I/O2) F10.1 L46.4 R304.1
CAN1H_: F10.2 J39.5(2) TP12.1
CAN1L: D89.2 D105.C(I/O1) F11.1 L46.3 R303.1
CAN1L_: F11.2 J39.4 TP13.1
CAN2_H: L47.1 U33.7(CANH)
CAN2_L: L47.2 U33.6(CANL)
CAN2_RX_M0: D107.A M5.75(I2C2_SDA_M1/EBC_GDSP/CAN2_RX_M0) R305.2
CAN2_RX_M0_: D107.C R306.2 U33.4(RXD)
CAN2_STB_IO: R307.2 U33.8(S)
CAN2_TX_M0: M5.74(I2C2_SCL_M1/EBC_SDSHR/CAN2_TX_M) Q15.2(SOURCE) R308.2
CAN2_TX_M0_: Q15.3(DRAIN) R309.2 U33.1(TXD)
CAN2H: D91.1 D106.A(I/O2) F12.1 L47.4 R311.1
CAN2H_: F12.2 J39.2(8) TP14.1
CAN2L: D91.2 D106.C(I/O1) F13.1 L47.3 R310.1
CAN2L_: F13.2 J39.1(10) TP15.1
CIF_CLKO_: C270.2 J28.9 R143.2
CIF_CLKOUT_SOC: M5.71(CIF_CLKOUT/EBC_GDCLK/PWM11_IR_M) R143.1
CIF_PDN0_: J28.6 R142.2
CIF_RST: C146.2 J28.5 R148.2 R377.2
CIF_RST_GPIO3_A3: M5.124(LCDC_D10/VOP_BT1120_D2/GMAC1_TX) R377.1
EDP_HPD: J19.20 R88.2
EDP_HPDIN_M1: M5.21(PWM3_IR/EDP_HPDIN_M1/PCIE30X1_W) R88.1
EDP_ON_: J21.4 Q17.2(SOURCE) R379.2 R380.2
EDP_PWM4: M5.22(PWM4/VOP_PWM_M0/PCIE30X1_PERSTN) R89.1 R108.1 U14.2(A)
EDP_PWM4_: J21.3 R89.2 U14.4(Y)
EDP_TX_AUXN: C99.2 M5.197(EDP_TX_AUXN)
EDP_TX_AUXN_: C99.1 J19.15 R374.2
EDP_TX_AUXP: C100.2 M5.198(EDP_TX_AUXP)
EDP_TX_AUXP_: C100.1 J19.16 R375.1
EDP_TX_D0N: C105.2 M5.203(EDP_TX_D0N)
EDP_TX_D0N_: C105.1 J19.7
EDP_TX_D0P: C106.2 M5.204(EDP_TX_D0P)
EDP_TX_D0P_: C106.1 J19.8
EDP_TX_D1N: C103.2 M5.201(EDP_TX_D1N)
EDP_TX_D1N_: C103.1 J19.9
EDP_TX_D1P: C104.2 M5.202(EDP_TX_D1P)
EDP_TX_D1P_: C104.1 J19.10
EDP_TX_D2N: C101.2 M5.199(EDP_TX_D2N)
EDP_TX_D2N_: C101.1 J19.11
EDP_TX_D2P: C102.2 M5.200(EDP_TX_D2P)
EDP_TX_D2P_: C102.1 J19.12
EDP_TX_D3N: C97.2 M5.195(EDP_TX_D3N)
EDP_TX_D3N_: C97.1 J19.17
EDP_TX_D3P: C98.2 M5.196(EDP_TX_D3P)
EDP_TX_D3P_: C98.1 J19.18
EXT_EN: M5.7(EXT_EN) R16.1
FE2.1_DM0: R51.1 U8.29(DM_I)
FE2.1_DM1: L8.2 U8.18(DM1)
FE2.1_DM1_: D18.5 D18.6 J8.11(2D-) L8.3
FE2.1_DM2: L9.2 U8.16(DM2)
FE2.1_DM2_: D21.2 D21.9 J9.2(1D-) L9.3
FE2.1_DM3: L10.2 U8.13(DM3)
FE2.1_DM3_: D21.5 D21.6 J9.11(2D-) L10.3
FE2.1_DM4: L12.2 U8.11(DM4)
FE2.1_DM4_: D25.1(I/O2) J10.2 L12.3
FE2.1_DM5: L14.2 U8.34(DM5)
FE2.1_DM5_: D28.1(I/O2) J11.2 L14.3
FE2.1_DM6: L15.2 U8.32(DM6)
FE2.1_DM6_: D31.1(I/O2) J12.2 L15.3
FE2.1_DM7: R335.2 U8.37(DM7)
FE2.1_DM7_: J41.36(USB_D-) R335.1
FE2.1_DP0: R50.1 U8.30(DP_1)
FE2.1_DP1: L8.1 U8.19(DP1)
FE2.1_DP1_: D18.4 D18.7 J8.12(2D+) L8.4
FE2.1_DP2: L9.1 U8.17(DP2)
FE2.1_DP2_: D21.1 D21.10 J9.3(1D+) L9.4
FE2.1_DP3: L10.1 U8.14(DP3)
FE2.1_DP3_: D21.4 D21.7 J9.12(2D+) L10.4
FE2.1_DP4: L12.1 U8.12(DP4)
FE2.1_DP4_: D26.1(I/O2) J10.3 L12.4
FE2.1_DP5: L14.1 U8.35(DP5)
FE2.1_DP5_: D29.1(I/O2) J11.3 L14.4
FE2.1_DP6: L15.1 U8.33(DP6)
FE2.1_DP6_: D32.1(I/O2) J12.3 L15.4
FE2.1_DP7: R336.2 U8.38(DP7)
FE2.1_DP7_: J41.38(USB_D+) R336.1
FE21_XIN: C64.2 R55.1 U8.22(XIN) XT1.1
FE21_XOUT: C65.2 R55.2 U8.23(XOUT) XT1.3
GM_VDDIO: C127.2 C130.2 C131.2 L29.1 R120.1 R122.1 U17.10(VDDIO) U17.13(PVDD2)
GMAC0_INT/PMEB_GPIO3_B0: M5.119(LCDC_D15/VOP_BT1120_D6/ETH1_REF) R215.2
GMAC0_MCLKINOUT: C171.2 M5.54(I2S2_SCLK_TX_M0/GMAC0_MCLKINOUT) R193.1 R194.1
GMAC0_MDC: M5.55(I2S2_LRCK_TX_M0/GMAC0_MDC/UART9) U24.13(MDC)
GMAC0_MDIO: M5.56(I2S2_SDO_M0/GMAC0_MDIO/UART9_CT) R220.1 U24.14(MDIO)
GMAC0_RSTN_GPIO3_A5: M5.122(LCDC_D12/VOP_BT1120_D4/GMAC1_RX) R219.1
GMAC0_RXCLK: C186.2 M5.41(SDMMC1_D2/GMAC0_RXCLK/UART7_RX_) R227.2
GMAC0_RXD0: M5.50(GMAC0_RXD0/UART1_CTSN_M0/SPI1_M) R223.2
GMAC0_RXD1: M5.51(I2S2_SCLK_RX_M0/GMAC0_RXD1/UART) R224.2
GMAC0_RXD2: M5.39(SDMMC1_D0/GMAC0_RXD2/UART6_RX_M) R225.2
GMAC0_RXD3: M5.40(SDMMC1_D1/GMAC0_RXD3/UART6_TX_M) R226.2
GMAC0_RXDV_CRS: M5.52(I2S2_LRCK_RX_M0/GMAC0_RXDV_CRS/) R228.2
GMAC0_TXCLK: C493.2 M5.44(SDMMC1_CLK/GMAC0_TXCLK/UART9_TX) R205.1
GMAC0_TXCLK_: C174.2 R205.2 U24.20(TXC)
GMAC0_TXD0: M5.47(GMAC0_TXD0/UART1_RX_M0/GPIO2_B3) R197.1
GMAC0_TXD0_: R197.2 U24.18(TXD0)
GMAC0_TXD1: M5.48(GMAC0_TXD1/UART1_TX_M0/GPIO2_B4) R198.1
GMAC0_TXD1_: R198.2 U24.17(TXD1)
GMAC0_TXD2: M5.42(SDMMC1_D3/GMAC0_TXD2/UART7_TX_M) R201.1
GMAC0_TXD2_: R201.2 U24.16(TXD2)
GMAC0_TXD3: M5.43(SDMMC1_CMD/GMAC0_TXD3/UART9_RX_) R202.1
GMAC0_TXD3_: R202.2 U24.15(TXD3)
GMAC0_TXEN: M5.49(GMAC0_TXEN/UART1_RTSN_M0/SPI1_C) R204.1
GMAC0_TXEN_: R204.2 U24.19(TXCTL)
GMAC1_INT/PMEB_GPIO3_C1: M5.110(LCDC_HSYNC/VOP_BT1120_D13/SPI1_) R262.2
GMAC1_MCLKINOUT_M1: C194.2 M5.70(CIF_CLKIN/EBC_SDCLK/GMAC1_MCLKI) R240.1 R241.1
GMAC1_MDC_M1: M5.73(CIF_HREF/EBC_SDLE/GMAC1_MDC_M1/) U25.13(MDC)
GMAC1_MDIO_M1: M5.72(CIF_VSYNC/EBC_SDOE/GMAC1_MDIO_M) R268.1 U25.14(MDIO)
GMAC1_RSTN_GPIO3_A6: M5.121(LCDC_D13/VOP_BT1120_CLK/GMAC1_T) R267.1
GMAC1_RXCLK_M1: C211.2 M5.84(CIF_D13/EBC_SDDO13/GMAC1_RXCLK_) R275.2
GMAC1_RXD0_M1: M5.80(CAM_CLKOUT0/EBC_SDCE1/GMAC1_RXD) R271.2
GMAC1_RXD1_M1: M5.79(CAM_CLKOUT1/EBC_SDCE2/GMAC1_RXD) R272.2
GMAC1_RXD2_M1: M5.86(CIF_D11/EBC_SDDO11/GMAC1_RXD2_M) R273.2
GMAC1_RXD3_M1: M5.85(CIF_D12/EBC_SDDO12/GMAC1_RXD3_M) R274.2
GMAC1_RXDV_CRS_M1: M5.78(ISP_PRELIGHT_TRIG/EBC_SDCE3/GMA) R276.2
GMAC1_TXCLK_M1: C494.2 M5.87(CIF_D10/EBC_SDDO10/GMAC1_TXCLK_) R253.1
GMAC1_TXCLK_M1_: C197.2 R253.2 U25.20(TXC)
GMAC1_TXD0_M1: M5.83(CIF_D14/EBC_SDDO14/GMAC1_TXD0_M) R244.1
GMAC1_TXD0_M1_: R244.2 U25.18(TXD0)
GMAC1_TXD1_M1: M5.82(CIF_D15/EBC_SDDO15/GMAC1_TXD1_M) R245.1
GMAC1_TXD1_M1_: R245.2 U25.17(TXD1)
GMAC1_TXD2_M1: M5.89(CIF_D8/EBC_SDDO8/GMAC1_TXD2_M1/) R248.1
GMAC1_TXD2_M1_: R248.2 U25.16(TXD2)
GMAC1_TXD3_M1: M5.88(CIF_D9/EBC_SDDO9/GMAC1_TXD3_M1/) R249.1
GMAC1_TXD3_M1_: R249.2 U25.15(TXD3)
GMAC1_TXEN_M1: M5.81(ISP_FLASHTRIGOUT/EBC_SDCE0/GMAC) R252.1
GMAC1_TXEN_M1_: R252.2 U25.19(TXCTL)
HDMI_TX_CEC_PORT: D108.2(I/O1) J18.13 Q5.3(DRAIN)
HDMI_TX_CLKN: L26.2 M5.153(HDMI_TX_CLKN)
HDMI_TX_CLKN_: D48.5 D48.6 J18.12 L26.3
HDMI_TX_CLKP: L26.1 M5.154(HDMI_TX_CLKP)
HDMI_TX_CLKP_: D48.4 D48.7 J18.10 L26.4
HDMI_TX_D0N: L25.2 M5.155(HDMI_TX_D0N)
HDMI_TX_D0N_: D48.2 D48.9 J18.9 L25.3
HDMI_TX_D0P: L25.1 M5.156(HDMI_TX_D0P)
HDMI_TX_D0P_: D48.1 D48.10 J18.7 L25.4
HDMI_TX_D1N: L24.2 M5.157(HDMI_TX_D1N)
HDMI_TX_D1N_: D47.5 D47.6 J18.6 L24.3
HDMI_TX_D1P: L24.1 M5.158(HDMI_TX_D1P)
HDMI_TX_D1P_: D47.4 D47.7 J18.4 L24.4
HDMI_TX_D2N: L23.2 M5.159(HDMI_TX_D2N)
HDMI_TX_D2N_: D47.2 D47.9 J18.3 L23.3
HDMI_TX_D2P: L23.1 M5.160(HDMI_TX_D2P)
HDMI_TX_D2P_: D47.1 D47.10 J18.1($PIN0) L23.4
HDMI_TX_HPD_PORT: D111.2(I/O1) J18.19 R85.2 R86.1
HDMI_TX_HPDIN: M5.148(HDMI_TX_HPDIN) R85.1
HDMI_TXDDC_SCL_PORT: D109.2(I/O1) J18.15 Q3.3(DRAIN) R82.2
HDMI_TXDDC_SDA_PORT: D110.2(I/O1) J18.16 Q4.3(DRAIN) R84.2
HDMITX_CEC_M0: M5.151(HDMITX_CEC_M0/SPI3_CS1_M1/GPIO4) Q5.2(SOURCE) R87.2
HOST_WAKE_BT: R162.2 R164.1 U23.6(BT_WAKE)
HOST_WAKE_BT_H_GPIO3_A2: M5.125(LCDC_D9/VOP_BT1120_D1/GMAC1_TXD) R162.1
HP_DET_H_GPIO0_C5: C82.2 M5.24(PWM6/SPI0_MISO_M0/PCIE30X2_WAKE) R72.2 R74.1
HP_SNS: M5.10(HP_SNS) R77.1
HPL_OUT: C86.2 M5.9(HPL_OUT) R73.1
HPR_OUT: C89.2 M5.11(HPR_OUT) R76.1
HUB_RST_: C60.2 R39.2 R48.2 U8.40(XRSTJ)
I2C1_SCL: M5.32(I2C1_SCL/CAN0_TX_M0/PCIE30X1_BU) R313.1 R316.2 R344.1
I2C1_SCL_RTC: R316.1 U34.6(SCL)
I2C1_SDA: M5.33(I2C1_SDA/CAN0_RX_M0/PCIE20_BUTT) R312.1 R317.2 R343.1
I2C1_SDA_RTC: R317.1 U34.5(SDA)
I2C2_SCL_M0: M5.34(I2C2_SCL_M0/SPI0_CLK_M0/PCIE20_) R318.1 R320.1
I2C2_SDA_M0: M5.35(I2C2_SDA_M0/SPI0_MOSI_M0/PCIE20) R319.1 R321.1
I2C3_SCL_M1: M5.114(LCDC_D20/VOP_BT1120_D11/GMAC1_T) R109.1 R113.1
I2C3_SDA_M1: M5.113(LCDC_D21/VOP_BT1120_D12/GMAC1_T) R110.1 R114.1
I2C4_SCL_M0: M5.76(I2C4_SCL_M0/EBC_GDOE/ETH1_REFCL) R144.1 R147.1
I2C4_SDA_M0: M5.77(I2C4_SDA_M0/EBC_VCOM/GMAC1_RXER) R145.1 R146.1
I2C5_SCL-HDMI: M5.150(HDMITX_SCL/I2C5_SCL_M1/GPIO4_C7) Q3.2(SOURCE) R81.2
I2C5_SDA-HDMI: M5.149(HDMITX_SDA/I2C5_SDA_M1/GPIO4_D0) Q4.2(SOURCE) R83.2
LAN0_A+: D72.6 J30.2(MDI_0+) R190.2
LAN0_A-: D72.1 J30.3(MDI_0-) R189.2
LAN0_B+: D72.3 J30.4(MDI_1+) R188.2
LAN0_B-: D72.4 J30.7(MDI_1-) R187.2
LAN0_C+: D71.6 J30.5(MDI_2+) R186.2
LAN0_C-: D71.1 J30.6(MDI_2-) R185.2
LAN0_D+: D71.3 J30.8(MDI_3+) R184.2
LAN0_D-: D71.4 J30.9(MDI_3-) R183.2
LAN1_A+: D74.6 J31.2(MDI_0+) R237.2
LAN1_A-: D74.1 J31.3(MDI_0-) R236.2
LAN1_B+: D74.3 J31.4(MDI_1+) R235.2
LAN1_B-: D74.4 J31.7(MDI_1-) R234.2
LAN1_C+: D73.6 J31.5(MDI_2+) R233.2
LAN1_C-: D73.1 J31.6(MDI_2-) R232.2
LAN1_D+: D73.3 J31.8(MDI_3+) R231.2
LAN1_D-: D73.4 J31.9(MDI_3-) R230.2
LCM_VIO_EN: Q7.1 Q10.1 R359.1 U38.15(IO1_2)
LVDS0_CLKN: D68.5 D68.6 J26.15(8) U17.27(A_CLKN)
LVDS0_CLKP: D68.4 D68.7 J26.16(23) U17.28(A_CLKP)
LVDS0_D0N: D66.2 D66.9 J26.7(4) U17.33(A_Y0N)
LVDS0_D0P: D66.1 D66.10 J26.8(19) U17.34(A_Y0P)
LVDS0_D1N: D66.5 D66.6 J26.9(5) U17.31(A_Y1N)
LVDS0_D1P: D66.4 D66.7 J26.10(20) U17.32(A_Y1P)
LVDS0_D2N: D68.2 D68.9 J26.11(6) U17.29(A_Y2N)
LVDS0_D2P: D68.1 D68.10 J26.12(21) U17.30(A_Y2P)
LVDS0_D3N: D69.2 D69.9 J26.17(9) U17.25(A_Y3N)
LVDS0_D3P: D69.1 D69.10 J26.18(24) U17.26(A_Y3P)
LVDS1_CLKN: D70.2 D70.9 J26.27(14) U17.41(B_CLKN)
LVDS1_CLKP: D70.1 D70.10 J26.28(29) U17.42(B_CLKP)
LVDS1_D0N: D69.5 D69.6 J26.19(10) U17.47(B_Y0N)
LVDS1_D0P: D69.4 D69.7 J26.20(25) U17.48(B_Y0P)
LVDS1_D1N: D67.2 D67.9 J26.21(11) U17.45(B_Y1N)
LVDS1_D1P: D67.1 D67.10 J26.22(26) U17.46(B_Y1P)
LVDS1_D2N: D67.5 D67.6 J26.23(12) U17.43(B_Y2N)
LVDS1_D2P: D67.4 D67.7 J26.24(27) U17.44(B_Y2P)
LVDS1_D3N: D70.5 D70.6 J26.29(15) U17.39(B_Y3N)
LVDS1_D3P: D70.4 D70.7 J26.30 U17.40(B_Y3P)
LVDS_ON_: J27.4 Q8.2(SOURCE) R127.2 R128.2
LVDS_PWM5: M5.23(PWM5/SPI0_CS1_M0/UART0_RTSN/GPI) R102.1 R130.1 U18.2(A)
LVDS_PWM5_: J27.3 R130.2 U18.4(Y)
LVDS_VIO: C138.2 C140.2 C141.2 J25.2 J25.4 J25.6 Q9.2(SOURCE) R129.1
LVDS_VIO_: C142.2 J26.1 J26.2(16) J26.3(2) Q9.3(DRAIN)
MIC1_INN: D41.1(I/O2) J15.4(D\E\T\) M5.13(MIC1_INN) R68.1 R70.1
MIC1_INP: C84.2 D42.1(I/O2) J16.2 M5.12(MIC1_INP) R78.2
MIPI_CAM0_PDN_L_GPIO2_C1: M5.53(I2S2_MCLK_M0/ETH0_REFCLKO_25M/U) R142.1
MIPI_CSI_CLKN: J28.17 R141.2
MIPI_CSI_CLKP: J28.18 R140.2
MIPI_CSI_D0N: J28.11 R133.2
MIPI_CSI_D0P: J28.12 R132.2
MIPI_CSI_D1N: J28.14 R135.2
MIPI_CSI_D1P: J28.15 R134.2
MIPI_CSI_D2N: J28.20 R137.2
MIPI_CSI_D2P: J28.21 R136.2
MIPI_CSI_D3N: J28.23 R139.2
MIPI_CSI_D3P: J28.24 R138.2
MIPI_CSI_RX_CLK0N: M5.170(MIPI_CSI_RX_CLK0N/PCIE30_REFCLK) R141.1
MIPI_CSI_RX_CLK0P: M5.169(MIPI_CSI_RX_CLK0P/PCIE30_REFCLK) R140.1
MIPI_CSI_RX_CLK1N: M5.172(MIPI_CSI_RX_CLK1N)
MIPI_CSI_RX_CLK1P: M5.171(MIPI_CSI_RX_CLK1P)
MIPI_CSI_RX_D0N: M5.162(MIPI_CSI_RX_D0N/PCIE30_TX0N) R133.1
MIPI_CSI_RX_D0P: M5.161(MIPI_CSI_RX_D0P/PCIE30_TX0P) R132.1
MIPI_CSI_RX_D1N: M5.164(MIPI_CSI_RX_D1N/PCIE30_TX1N) R135.1
MIPI_CSI_RX_D1P: M5.163(MIPI_CSI_RX_D1P/PCIE30_TX1P) R134.1
MIPI_CSI_RX_D2N: M5.166(MIPI_CSI_RX_D2N/PCIE30_RX0N) R137.1
MIPI_CSI_RX_D2P: M5.165(MIPI_CSI_RX_D2P/PCIE30_RX0P) R136.1
MIPI_CSI_RX_D3N: M5.168(MIPI_CSI_RX_D3N/PCIE30_RX1N) R139.1
MIPI_CSI_RX_D3P: M5.167(MIPI_CSI_RX_D3P/PCIE30_RX1P) R138.1
MIPI_DSI_TX0_CLKN: M5.142(MIPI_DSI_TX0_CLKN/LVDS_TX0_CLKN) R98.1 U17.19(DACN)
MIPI_DSI_TX0_CLKN_: D53.2 D53.9 J22.27 R98.2
MIPI_DSI_TX0_CLKP: M5.143(MIPI_DSI_TX0_CLKP/LVDS_TX0_CLKP) R97.1 U17.18(DACP)
MIPI_DSI_TX0_CLKP_: D53.1 D53.10 J22.26 R97.2
MIPI_DSI_TX0_D0N: M5.146(MIPI_DSI_TX0_D0N/LVDS_TX0_D0N) R94.1 U17.15(DA0N)
MIPI_DSI_TX0_D0N_: D55.2(I/O1) J22.33 R94.2
MIPI_DSI_TX0_D0P: M5.147(MIPI_DSI_TX0_D0P/LVDS_TX0_D0P) R93.1 U17.14(DA0P)
MIPI_DSI_TX0_D0P_: D54.2(I/O1) J22.32 R93.2
MIPI_DSI_TX0_D1N: M5.144(MIPI_DSI_TX0_D1N/LVDS_TX0_D1N) R96.1 U17.17(DA1N)
MIPI_DSI_TX0_D1N_: D53.5 D53.6 J22.30 R96.2
MIPI_DSI_TX0_D1P: M5.145(MIPI_DSI_TX0_D1P/LVDS_TX0_D1P) R95.1 U17.16(DA1P)
MIPI_DSI_TX0_D1P_: D53.4 D53.7 J22.29 R95.2
MIPI_DSI_TX0_D2N: M5.140(MIPI_DSI_TX0_D2N/LVDS_TX0_D2N) R100.1 U17.21(DA2N)
MIPI_DSI_TX0_D2N_: D52.5 D52.6 J22.24 R100.2
MIPI_DSI_TX0_D2P: M5.141(MIPI_DSI_TX0_D2P/LVDS_TX0_D2P) R99.1 U17.20(DA2P)
MIPI_DSI_TX0_D2P_: D52.4 D52.7 J22.23 R99.2
MIPI_DSI_TX0_D3N: M5.138(MIPI_DSI_TX0_D3N/LVDS_TX0_D3N) R101.1 U17.23(DA3N)
MIPI_DSI_TX0_D3N_: D52.2 D52.9 J22.21 R101.2
MIPI_DSI_TX0_D3P: M5.139(MIPI_DSI_TX0_D3P/LVDS_TX0_D3P) R92.1 U17.22(DA3P)
MIPI_DSI_TX0_D3P_: D52.1 D52.10 J22.20 R92.2
MIPI_DSI_TX0_RST: C118.2 J22.36 R103.2
MIPI_DSI_TX1_CLKN: D58.2 D58.9 J23.27 M5.132(MIPI_DSI_TX1_CLKN)
MIPI_DSI_TX1_CLKP: D58.1 D58.10 J23.26 M5.133(MIPI_DSI_TX1_CLKP)
MIPI_DSI_TX1_D0N: D61.2(I/O1) J23.33 M5.136(MIPI_DSI_TX1_D0N)
MIPI_DSI_TX1_D0P: D59.2(I/O1) J23.32 M5.137(MIPI_DSI_TX1_D0P)
MIPI_DSI_TX1_D1N: D58.5 D58.6 J23.30 M5.134(MIPI_DSI_TX1_D1N)
MIPI_DSI_TX1_D1P: D58.4 D58.7 J23.29 M5.135(MIPI_DSI_TX1_D1P)
MIPI_DSI_TX1_D2N: D57.5 D57.6 J23.24 M5.130(MIPI_DSI_TX1_D2N)
MIPI_DSI_TX1_D2P: D57.4 D57.7 J23.23 M5.131(MIPI_DSI_TX1_D2P)
MIPI_DSI_TX1_D3N: D57.2 D57.9 J23.21 M5.128(MIPI_DSI_TX1_D3N)
MIPI_DSI_TX1_D3P: D57.1 D57.10 J23.20 M5.129(MIPI_DSI_TX1_D3P)
MIPI_DSI_TX1_RST: C125.2 J23.36 R119.2
MIPI_TX0_BL_PWM5: R102.2 R105.1 U15.4(EN)
MIPI_TX1_BL_PWM4: R108.2 R116.1 U16.4(EN)
MPU6500_AD0: R323.2 R324.1 U35.9(SDO/AD0)
NSD_CD: D8.1(I/O2) J3.9(CD) R24.2
PCA9539_A0: R364.2 R366.1 U38.21(A0)
PCA9539_A1: R363.2 R365.1 U38.2(A1)
PCA9539_I2C_SCL: R344.2 U38.22(SCL)
PCA9539_I2C_SDA: R343.2 U38.23(SDA)
PCA9539_INT: R345.2 U38.1(INT#)
PCA9539_INT_GPIO4_C4: M5.29(EDP_HPDIN_M0/SPDIF_TX_M2/SATA2_) R345.1
PCA9539_IO0_0: R36.1 R353.1 U5.4(EN) U38.4(IO0_0)
PCA9539_IO0_1: R39.1 R352.1 U38.5(IO0_1)
PCA9539_IO0_2: R40.1 R351.1 U6.4(EN) U38.6(IO0_2)
PCA9539_IO0_3: R42.1 R350.1 U7.4(EN) U38.7(IO0_3)
PCA9539_IO0_4: R47.1 R349.1 U9.4(EN) U38.8(IO0_4)
PCA9539_IO0_5: R52.1 R348.1 U10.4(EN) U38.9(IO0_5)
PCA9539_IO0_6: R56.1 R347.1 U11.4(EN) U38.10(IO0_6)
PCA9539_IO0_7: Q13.1 R346.1 U38.11(IO0_7)
PCA9539_IO1_0: Q1.1 R361.1 U38.13(IO1_0)
PCA9539_IO1_1: Q2.1 R360.1 U38.14(IO1_1)
PCA9539_IO1_3: Q8.3(DRAIN) R126.2 R128.1 R358.1 U38.16(IO1_3)
PCA9539_IO1_4: R357.1 R382.1 U38.17(IO1_4) U40.4(EN)
PCA9539_IO1_5: R342.1 R356.1 U38.18(IO1_5)
PCA9539_IO1_6: Q17.3(DRAIN) R355.1 R378.2 R379.1 U38.19(IO1_6)
PCA9539_IO1_7: R354.1 U38.20(IO1_7)
PCA9539_RST: C269.2 R362.2 U38.3(RST#)
PCIE20_REFCLKN: M5.178(PCIE20_REFCLKN) R331.2
PCIE20_REFCLKP: M5.177(PCIE20_REFCLKP) R328.2
PCIE20_RXN: M5.176(PCIE20_RXN/SATA2_RXN/QSGMII_RXN) R333.2
PCIE20_RXN_: R333.1 U36.41(PETN0)
PCIE20_RXP: M5.175(PCIE20_RXP/SATA2_RXP/QSGMII_RXP) R332.2
PCIE20_RXP_: R332.1 U36.43(PETP0)
PCIE20_TXN: C251.2 M5.174(PCIE20_TXN/SATA2_TXN/QSGMII_TXN)
PCIE20_TXN_: C251.1 U36.47(PERN0)
PCIE20_TXP: C249.2 M5.173(PCIE20_TXP/SATA2_TXP/QSGMII_TXP)
PCIE20_TXP_: C249.1 U36.49(PERP0)
PHY0_CLKOUT125: R193.2 U24.35(CLKOUT)
PHY0_G_LED-: J30.12(G_LED-) R192.1
PHY0_LED0/CFG_EXT: R195.2 R196.1 U24.32(LED0/CFG_EXT)
PHY0_LED1/CFG_LDO0: C173.2 J30.11(G_LED+) R203.2 U24.33(LED1/CFG_LDO0)
PHY0_LED2/CFG_LDO1: C172.2 J30.13(Y_LED-) R199.2 R200.1 U24.34(LED2/CFG_LDO1)
PHY0_MDI0+: R190.1 U24.1(MDI[0]+)
PHY0_MDI0-: R189.1 U24.2(MDI[0]-)
PHY0_MDI1+: R188.1 U24.4(MDI[1]+)
PHY0_MDI1-: R187.1 U24.5(MDI[1]-)
PHY0_MDI2+: R186.1 U24.6(MDI[2]+)
PHY0_MDI2-: R185.1 U24.7(MDI[2]-)
PHY0_MDI3+: R184.1 U24.9(MDI[3]+)
PHY0_MDI3-: R183.1 U24.10(MDI[3]-)
PHY0_REG_OUT: L32.1 U24.30(REG_OUT)
PHY0_RSTN: C182.2 R218.2 R219.2 U24.12(PHYRSTB)
PHY0_RXCLK/PHYAD1: C496.2 R208.2 R209.1 R227.1 U24.27(RXC/PHYAD1)
PHY0_RXD0/RXDLY: R210.2 R211.1 R223.1 U24.25(RXD0/RXDLY)
PHY0_RXD1/TXDLY: R213.2 R214.1 R224.1 U24.24(RXD1/TXDLY)
PHY0_RXD2/PLLOFF: R216.2 R217.1 R225.1 U24.23(RXD2/PLLOFF)
PHY0_RXD3/PHYAD0: R207.1 R226.1 U24.22(RXD3/PHYAD0)
PHY0_RXDV/PHYAD2: R206.2 R228.1 U24.26(RXCTL/PHYAD2)
PHY0_XTALIN: C169.2 U24.36(XTAL_IN) XT4.3
PHY0_XTALOUT: C170.2 U24.37(XTAL_OUT/EXT_CLK) XT4.1
PHY0_Y_LED+: J30.14(Y_LED+) R191.1
PHY1_CLKOUT125: R240.2 U25.35(CLKOUT)
PHY1_G_LED-: J31.12(G_LED-) R239.1
PHY1_LED0/CFG_EXT: R242.2 R243.1 U25.32(LED0/CFG_EXT)
PHY1_LED1/CFG_LDO0: C196.2 J31.11(G_LED+) R250.2 U25.33(LED1/CFG_LDO0)
PHY1_LED2/CFG_LDO1: C195.2 J31.13(Y_LED-) R246.2 R247.1 U25.34(LED2/CFG_LDO1)
PHY1_MDI0+: R237.1 U25.1(MDI[0]+)
PHY1_MDI0-: R236.1 U25.2(MDI[0]-)
PHY1_MDI1+: R235.1 U25.4(MDI[1]+)
PHY1_MDI1-: R234.1 U25.5(MDI[1]-)
PHY1_MDI2+: R233.1 U25.6(MDI[2]+)
PHY1_MDI2-: R232.1 U25.7(MDI[2]-)
PHY1_MDI3+: R231.1 U25.9(MDI[3]+)
PHY1_MDI3-: R230.1 U25.10(MDI[3]-)
PHY1_REG_OUT: L33.1 U25.30(REG_OUT)
PHY1_RSTN: C207.2 R266.2 R267.2 U25.12(PHYRSTB)
PHY1_RXCLK/PHYAD1: C497.2 R254.2 R255.1 R275.1 U25.27(RXC/PHYAD1)
PHY1_RXD0/RXDLY: R257.2 R258.1 R271.1 U25.25(RXD0/RXDLY)
PHY1_RXD1/TXDLY: R260.2 R261.1 R272.1 U25.24(RXD1/TXDLY)
PHY1_RXD2/PLLOFF: R263.2 R264.1 R273.1 U25.23(RXD2/PLLOFF)
PHY1_RXD3/PHYAD0: R251.1 R274.1 U25.22(RXD3/PHYAD0)
PHY1_RXDV/PHYAD2: R256.2 R276.1 U25.26(RXCTL/PHYAD2)
PHY1_XTALIN: C192.2 U25.36(XTAL_IN) XT5.3
PHY1_XTALOUT: C193.2 U25.37(XTAL_OUT/EXT_CLK) XT5.1
PHY1_Y_LED+: J31.14(Y_LED+) R238.1
PWM7_IR: D102.1(I/O2) J14.7 M5.25(PWM7_IR/SPI0_CS0_M0/PCIE30X2_PE)
REFCLK_GM8775C: R125.1 U17.24(REFCLK)
REFCLKN_: R331.1 U36.53(PEFCLKN)
REFCLKP_: R328.1 U36.55(PEFCLKP)
REXT: R54.1 U8.27(REXT)
RK809_PWRON: D34.1(I/O2) J13.2 M5.8(RK809_PWRON)
RK809_VDC: C14.2 M5.6(RK809_VDC) R7.2 R10.1
RS485_5_DM: L42.1 R289.2 U29.7(B)
RS485_5_DP: L43.1 R292.1 U29.6(A)
RS485_5_RW_EN: R293.1 U28.4 U29.2(\\R\E) U29.3(DE)
RS485_7_DM: L44.1 R296.2 U31.7(B)
RS485_7_DP: L45.1 R298.1 U31.6(A)
RS485_7_RW_EN: R299.1 U30.4 U31.2(\\R\E) U31.3(DE)
RSET0: R212.2 U24.39(RSET)
RSET1: R259.2 U25.39(RSET)
RTCIC_32KOUT: R177.1 U34.7(CLKOUT)
S0RX: D103.2 F14.1 L41.2 R383.2
S0RX_: F14.2 J32.3 TP3.1
S0TX: D103.1 F15.1 L40.2 R278.2
S0TX_: F15.2 J32.2 TP2.1
S3RX_M1: D78.2 F2.1 L35.2 R384.2
S3RX_M1_: F2.2 J33.3 TP4.1
S3TX_M1: D78.1 F3.1 L34.2 R282.2
S3TX_M1_: F3.2 J33.2 TP5.1
S4RX_M1: D81.2 F4.1 L37.2 R385.2
S4RX_M1_: F4.2 J34.3 TP6.1
S4TX_M1: D81.1 F5.1 L36.2 R284.2
S4TX_M1_: F5.2 J34.2 TP7.1
S5RX_M1: D82.C U29.1(RO)
S5RX_M1/RS485-A5: D75.C(I/O1) D85.2 F6.1 L39.2 L43.2 R290.2
S5RX_M1_: F6.2 J35.3 TP8.1
S5TX_M1: R286.2 U29.4(DI)
S5TX_M1/RS485-B5: D75.A(I/O2) D85.1 F7.1 L38.2 L42.2 R290.1
S5TX_M1_: F7.2 J35.2 TP9.1
S7RX_M1: D86.C U31.1(RO)
S7RX_M1/RS485-A7: D87.2 D104.C(I/O1) F8.1 L45.2 R297.2
S7RX_M1_: F8.2 J36.3 TP10.1
S7TX_M1: R291.2 U31.4(DI)
